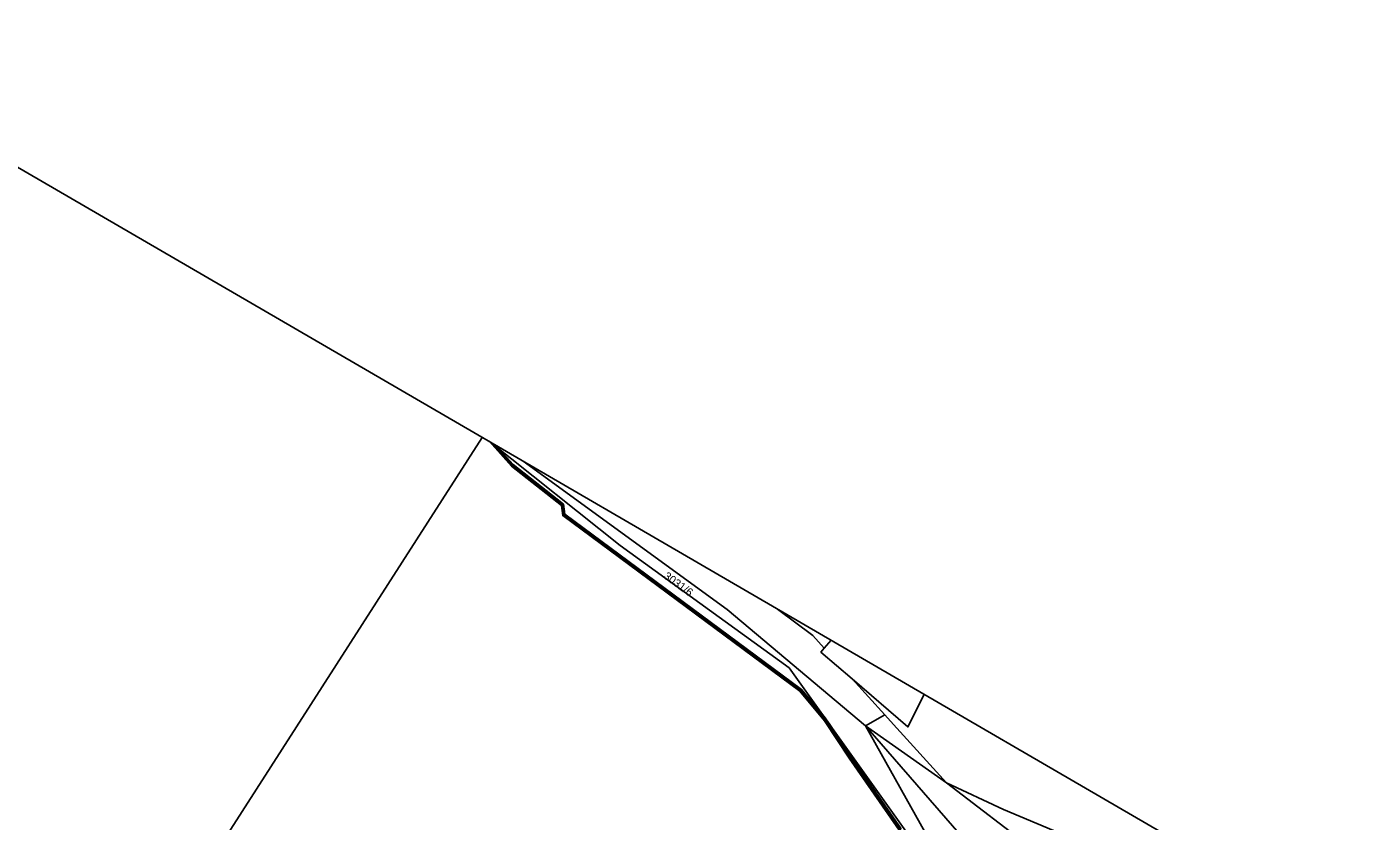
# Model space of a CAD drawing. Extents: x -621168 to -620292, y -1122748 to -1122069.
# Drawn here: x -620574.7 to -620292.4, y -1122465.1 to -1122296.3 of the extents above; entities that cross this region are included whole.
import ezdxf

# ---------------------------------------------------------------- set-up
doc = ezdxf.new("R2010")
doc.units = 0
for name, color, linetype in [('Hranice parcel', 7, 'Continuous'), ('itself', 7, 'Continuous'), ('Parcelní čísla', 7, 'Continuous'), ('Rámečky-tisk', 7, 'Continuous'), ('Vnitřní kresba', 7, 'Continuous'), ('Věcná břemena k části', 7, 'Continuous')]:
    doc.layers.add(name, color=color, linetype=linetype)

msp = doc.modelspace()

# ---------------------------------------------------------------- linework, layer by layer
at = {"layer": 'Hranice parcel'}
for p, q in [((-620548.9, -1122494.24), (-620477.85, -1122383.56)), ((-620405.21, -1122428.32), (-620403.76, -1122426.64)), ((-620379.27, -1122456.9), (-620396.46, -1122444.78)), ((-620396.46, -1122444.78), (-620369.79, -1122492.47)), ((-620379.27, -1122456.9), (-620353.42, -1122476.62))]:
    msp.add_line(p, q, dxfattribs=at)
for points in [[(-620476.11, -1122384.57), (-620448.57, -1122406.53), (-620412.63, -1122432.52), (-620369.79, -1122492.47)], [(-620396.46, -1122444.78), (-620425.84, -1122420.12), (-620469.18, -1122388.6)], [(-620415.14, -1122420.02), (-620407.66, -1122425.61), (-620405.21, -1122428.32)], [(-620405.21, -1122428.32), (-620405.92, -1122429.14), (-620399.27, -1122434.86)], [(-620383.98, -1122438.14), (-620387.43, -1122445.04), (-620399.27, -1122434.86)], [(-620399.27, -1122434.86), (-620392.37, -1122442.46), (-620390.49, -1122444.54), (-620379.27, -1122456.9)], [(-620353.03, -1122491.08), (-620367.06, -1122478.57), (-620396.46, -1122444.78)], [(-620379.27, -1122456.9), (-620367.13, -1122462.61), (-620348.06, -1122470.58), (-620333.32, -1122476.77)]]:
    msp.add_lwpolyline(points, dxfattribs=at)
at = {"layer": 'itself'}
msp.add_lwpolyline([(-620475.64, -1122384.85), (-620471.44, -1122389.5), (-620460.82, -1122397.87), (-620460.54, -1122400.03), (-620410.2, -1122437.25), (-620404.97, -1122443.58), (-620399.73, -1122451.56), (-620389.1, -1122466.86), (-620376.31, -1122486.53), (-620373.53, -1122493.65), (-620373.92, -1122499.17), (-620380.47, -1122515.82), (-620389.96, -1122532.36)], dxfattribs=at)
at = {"layer": 'Rámečky-tisk'}
msp.add_lwpolyline([(-620441.66, -1122748.16), (-620292.37, -1122491.41), (-621018.54, -1122069.17)], dxfattribs=at)
at = {"layer": 'Vnitřní kresba'}
msp.add_line((-620392.37, -1122442.46), (-620396.46, -1122444.78), dxfattribs=at)
at = {"layer": 'Věcná břemena k části'}
for p, q in [((-620476.1, -1122384.58), (-620476.34, -1122384.43)), ((-620474.94, -1122385.25), (-620476.1, -1122384.58))]:
    msp.add_line(p, q, dxfattribs=at)
for points in [[(-620476.34, -1122384.43), (-620471.61, -1122389.68), (-620461.05, -1122398), (-620460.77, -1122400.17), (-620410.37, -1122437.43), (-620405.17, -1122443.73), (-620399.94, -1122451.7), (-620389.31, -1122467)], [(-620476.1, -1122384.58), (-620474.12, -1122386.16), (-620474.94, -1122385.25)], [(-620388.89, -1122466.72), (-620399.52, -1122451.42), (-620404.03, -1122444.55), (-620405.25, -1122442.85), (-620410.03, -1122437.07), (-620460.31, -1122399.89), (-620460.59, -1122397.74), (-620471.27, -1122389.32), (-620474.12, -1122386.16), (-620476.1, -1122384.58)]]:
    msp.add_lwpolyline(points, dxfattribs=at)

# ---------------------------------------------------------------- texts
at = {"layer": 'Parcelní čísla'}
msp.add_text('3031/6', height=1.7, rotation=324, dxfattribs=at).set_placement((-620439.48, -1122413.34))

doc.saveas('drawing.dxf')
